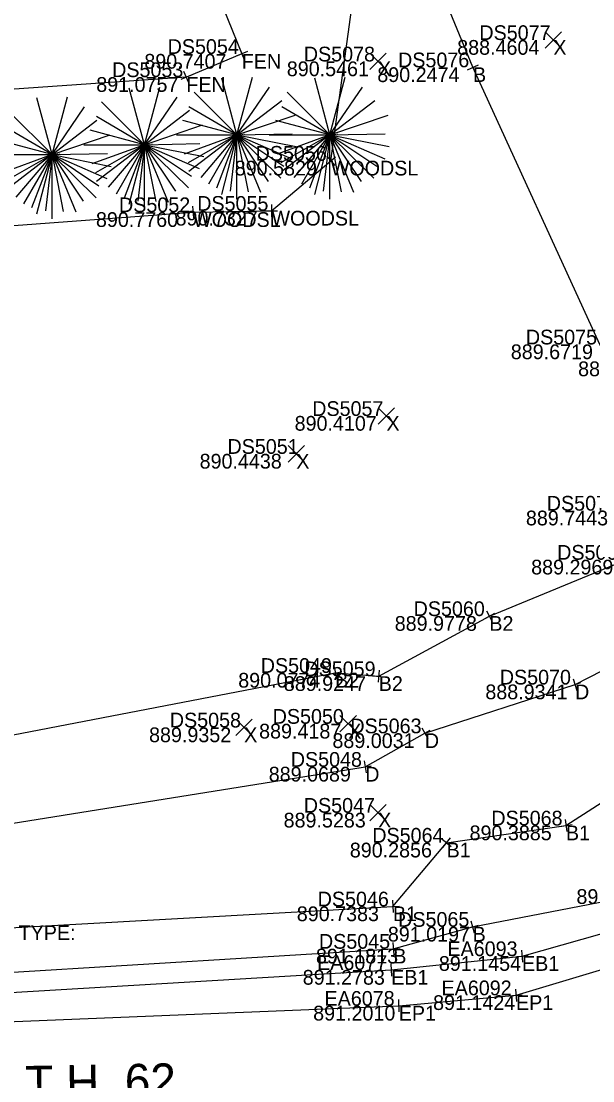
# Model space of a CAD drawing. Extents: x 179044 to 189691, y 286531 to 301257.
# Drawn here: x 180099.2 to 180145.7, y 300591.3 to 300677.6 of the extents above; entities that cross this region are included whole.
import ezdxf

# ---------------------------------------------------------------- set-up
doc = ezdxf.new("R2010")
doc.units = 0
for name, color, linetype in [('Default', 7, 'Continuous'), ('DR_X_Ditch', 7, 'Continuous'), ('PV_X_EOP', 7, 'Continuous'), ('PV_X_Shoulder_Aggregate', 7, 'Continuous'), ('RD_X_Fence', 7, 'Continuous'), ('SV_X_Break_Lines', 7, 'Continuous'), ('SV_X_Random_Point', 7, 'Continuous'), ('SV_X_Shot_Marker', 7, 'Continuous'), ('SV_X_Text_Comment', 7, 'Continuous'), ('SV_X_Text_Description', 7, 'Continuous'), ('SV_X_Text_Elevation', 7, 'Continuous'), ('SV_X_Text_Name', 7, 'Continuous'), ('VG_X_Cells', 7, 'Continuous'), ('VG_X_Text', 7, 'Continuous'), ('VG_X_Tree_Line_Rt', 7, 'Continuous')]:
    doc.layers.add(name, color=color, linetype=linetype)

msp = doc.modelspace()

# ---------------------------------------------------------------- linework, layer by layer
at = {"layer": 'DR_X_Ditch'}
msp.add_lwpolyline([(179564.56, 300599.962), (179672.339, 300603.26), (179771.172, 300605.494), (179880.337, 300606.441), (179984.937, 300607.328), (180077.947, 300608.965), (180127.19, 300616.843), (180132.045, 300619.573), (180144.286, 300623.545), (180155.547, 300629.29), (180160.465, 300633.547)], dxfattribs=at)
at = {"layer": 'PV_X_EOP'}
msp.add_lwpolyline([(179370.831, 300591.751), (179475.585, 300592.875), (179659.265, 300594.122), (179770.991, 300594.472), (179880.742, 300594.985), (179984.71, 300595.495), (180079.288, 300595.313), (180129.921, 300597.382), (180139.474, 300598.239), (180154.233, 300602.666), (180170.463, 300611.587), (180179.633, 300620.691), (180184.59, 300626.615), (180188.342, 300633.535), (180190.62, 300639.725), (180171.316, 300693.382), (180137.201, 300785.062), (180098.417, 300888.791)], dxfattribs=at)
at = {"layer": 'PV_X_Shoulder_Aggregate'}
msp.add_lwpolyline([(179563.565, 300594.924), (179658.987, 300595.359), (179770.596, 300596.259), (179881.565, 300597.129), (179984.257, 300597.357), (180079.139, 300597.322), (180129.307, 300600.299), (180139.964, 300601.425), (180153.02, 300605.118), (180169.97, 300613.883), (180177.635, 300623.691), (180181.654, 300635.111), (180182.998, 300649.235), (180167.771, 300692.69), (180134.639, 300784.201), (180095.484, 300888.508)], dxfattribs=at)
at = {"layer": 'RD_X_Fence'}
msp.add_lwpolyline([(180033.616, 300896.161), (180069.423, 300800.637), (180103.118, 300709.458), (180117.129, 300674.9), (180112.616, 300673.011), (180037.359, 300667.77), (179974.547, 300663.799), (179875.902, 300656.609), (179766.558, 300649.439), (179668.068, 300642.7), (179565.54, 300636.358)], dxfattribs=at)
at = {"layer": 'SV_X_Break_Lines'}
for points in [[(179564.638, 300606.986), (179671.768, 300606.922), (179771.087, 300608.912), (179880.599, 300615.611), (179986.884, 300616.02), (180078.033, 300615.521), (180124.742, 300624.492), (180128.289, 300624.221), (180137.303, 300629.118), (180148.459, 300633.708), (180154.503, 300636.496), (180146.307, 300651.241), (180135.969, 300673.811), (180118.542, 300716.074), (180095.911, 300772.35), (180076.611, 300824.96), (180047.5, 300900.199)], [(179564.191, 300598.682), (179770.809, 300601.942), (179880.33, 300600.557), (179984.707, 300602.17), (180076.298, 300602.513), (180129.447, 300605.473), (180133.823, 300610.665), (180143.543, 300612.063), (180154.911, 300619.358), (180168.807, 300625.749), (180172.898, 300631.66), (180174.527, 300641.071), (180168.307, 300660.619), (180157.537, 300688.57), (180123.865, 300779.294), (180087.271, 300883.216)], [(179564.385, 300595.92), (179672.75, 300596.68), (179770.459, 300597.562), (179880.51, 300598.544), (179984.703, 300599.007), (180076.342, 300598.773), (180129.476, 300602.027), (180135.94, 300603.814), (180151.807, 300606.879), (180162.976, 300612.722)]]:
    msp.add_lwpolyline(points, dxfattribs=at)
at = {"layer": 'SV_X_Random_Point'}
for p, q in [((180141.85, 300675.364), (180143.183, 300676.699)), ((180141.85, 300676.699), (180143.183, 300675.364)), ((180127.557, 300673.621), (180128.891, 300674.956)), ((180127.557, 300674.956), (180128.891, 300673.621)), ((180128.252, 300644.749), (180129.585, 300646.084)), ((180128.252, 300646.084), (180129.585, 300644.749)), ((180120.91, 300641.663), (180122.243, 300642.998)), ((180120.91, 300642.998), (180122.243, 300641.663)), ((180116.658, 300619.382), (180117.991, 300620.717)), ((180116.658, 300620.717), (180117.991, 300619.382)), ((180125.134, 300619.681), (180126.467, 300621.016)), ((180125.134, 300621.016), (180126.467, 300619.681)), ((180127.573, 300612.433), (180128.906, 300613.768)), ((180127.573, 300613.768), (180128.906, 300612.433))]:
    msp.add_line(p, q, dxfattribs=at)
at = {"layer": 'SV_X_Shot_Marker'}
for p, q in [((180117.592, 300675.088), (180116.665, 300674.712)), ((180116.941, 300675.364), (180117.317, 300674.437)), ((180117.129, 300674.9), (180117.129, 300674.9)), ((180135.514, 300673.603), (180136.423, 300674.02)), ((180136.177, 300673.357), (180135.76, 300674.266)), ((180135.969, 300673.811), (180135.969, 300673.811)), ((180113.077, 300673.204), (180112.155, 300672.818)), ((180112.809, 300672.55), (180112.423, 300673.472)), ((180112.616, 300673.011), (180112.616, 300673.011)), ((180124, 300665.879), (180124.765, 300666.523)), ((180124.06, 300666.583), (180124.705, 300665.819)), ((180124.383, 300666.201), (180124.383, 300666.201)), ((180113.13, 300662.509), (180113.204, 300661.511)), ((180119.541, 300662.624), (180119.559, 300661.624)), ((180112.668, 300661.973), (180113.666, 300662.047)), ((180113.167, 300662.01), (180113.167, 300662.01)), ((180119.05, 300662.115), (180120.05, 300662.133)), ((180119.55, 300662.124), (180119.55, 300662.124)), ((180136.864, 300628.879), (180137.742, 300629.356)), ((180137.064, 300629.557), (180137.542, 300628.678)), ((180137.303, 300629.118), (180137.303, 300629.118)), ((180124.251, 300624.398), (180125.233, 300624.587)), ((180124.648, 300624.983), (180124.837, 300624.001)), ((180124.742, 300624.492), (180124.742, 300624.492)), ((180128.327, 300624.72), (180128.25, 300623.723)), ((180127.79, 300624.259), (180128.787, 300624.183)), ((180128.289, 300624.221), (180128.289, 300624.221)), ((180143.81, 300623.391), (180144.761, 300623.699)), ((180144.132, 300624.02), (180144.44, 300623.069)), ((180144.286, 300623.545), (180144.286, 300623.545)), ((180131.609, 300619.328), (180132.481, 300619.818)), ((180131.8, 300620.009), (180132.29, 300619.137)), ((180132.045, 300619.573), (180132.045, 300619.573)), ((180126.696, 300616.764), (180127.683, 300616.922)), ((180127.111, 300617.337), (180127.269, 300616.35)), ((180127.19, 300616.843), (180127.19, 300616.843)), ((180143.472, 300612.558), (180143.614, 300611.568)), ((180143.048, 300611.992), (180144.038, 300612.134)), ((180143.543, 300612.063), (180143.543, 300612.063)), ((180133.441, 300610.988), (180134.205, 300610.343)), ((180133.501, 300610.283), (180134.145, 300611.048)), ((180133.823, 300610.665), (180133.823, 300610.665)), ((180129.42, 300605.972), (180129.475, 300604.974)), ((180128.948, 300605.445), (180129.947, 300605.501)), ((180129.447, 300605.473), (180129.447, 300605.473)), ((180135.458, 300603.681), (180136.422, 300603.947)), ((180135.807, 300604.296), (180136.073, 300603.332)), ((180135.94, 300603.814), (180135.94, 300603.814)), ((180128.977, 300601.997), (180129.975, 300602.058)), ((180129.445, 300602.526), (180129.507, 300601.528)), ((180129.476, 300602.027), (180129.476, 300602.027)), ((180139.467, 300601.372), (180140.462, 300601.478)), ((180139.912, 300601.922), (180140.017, 300600.928)), ((180139.964, 300601.425), (180139.964, 300601.425)), ((180128.808, 300600.27), (180129.806, 300600.329)), ((180129.277, 300600.799), (180129.337, 300599.8)), ((180129.307, 300600.299), (180129.307, 300600.299)), ((180139.429, 300598.737), (180139.519, 300597.741)), ((180129.901, 300597.882), (180129.941, 300596.882)), ((180138.976, 300598.194), (180139.972, 300598.284)), ((180139.474, 300598.239), (180139.474, 300598.239)), ((180129.421, 300597.362), (180130.421, 300597.402)), ((180129.921, 300597.382), (180129.921, 300597.382))]:
    msp.add_line(p, q, dxfattribs=at)
at = {"layer": 'VG_X_Cells'}
for p, q in [((180116.735, 300668.307), (180115.5, 300672.921)), ((180116.735, 300668.307), (180117.992, 300673.006)), ((180124.31, 300668.307), (180123.075, 300672.921)), ((180124.31, 300668.307), (180125.567, 300673.006)), ((180109.203, 300667.505), (180107.968, 300672.118)), ((180109.203, 300667.505), (180110.459, 300672.203)), ((180116.735, 300668.307), (180119.39, 300672.192)), ((180124.31, 300668.307), (180126.965, 300672.192)), ((180101.67, 300666.702), (180100.435, 300671.316)), ((180101.67, 300666.702), (180102.927, 300671.401)), ((180109.203, 300667.505), (180111.858, 300671.39)), ((180116.735, 300668.307), (180113.245, 300671.794)), ((180116.735, 300668.307), (180120.392, 300671.112)), ((180124.31, 300668.307), (180120.82, 300671.794)), ((180124.31, 300668.307), (180127.967, 300671.112)), ((180101.67, 300666.702), (180104.325, 300670.587)), ((180109.203, 300667.505), (180105.713, 300670.992)), ((180109.203, 300667.505), (180112.859, 300670.31)), ((180116.735, 300668.307), (180112.829, 300670.604)), ((180124.31, 300668.307), (180120.404, 300670.604)), ((180101.67, 300666.702), (180098.18, 300670.189)), ((180101.67, 300666.702), (180105.327, 300669.507)), ((180109.203, 300667.505), (180105.296, 300669.802)), ((180116.735, 300668.307), (180112.322, 300669.491)), ((180116.735, 300668.307), (180121.472, 300669.914)), ((180124.31, 300668.307), (180119.897, 300669.491)), ((180124.31, 300668.307), (180129.047, 300669.914)), ((180101.67, 300666.702), (180097.763, 300668.999)), ((180109.203, 300667.505), (180104.789, 300668.688)), ((180109.203, 300667.505), (180113.939, 300669.112)), ((180101.67, 300666.702), (180097.257, 300667.886)), ((180101.67, 300666.702), (180106.407, 300668.309)), ((180111.8, 300668.307), (180116.735, 300668.307)), ((180116.735, 300668.307), (180112.445, 300666.746)), ((180116.735, 300668.307), (180112.752, 300666.026)), ((180116.735, 300668.307), (180112.829, 300665.312)), ((180116.735, 300668.307), (180113.79, 300664.841)), ((180116.735, 300668.307), (180114.417, 300664.292)), ((180116.735, 300668.307), (180115.07, 300663.967)), ((180116.735, 300668.307), (180115.472, 300663.451)), ((180116.735, 300668.307), (180116.194, 300663.716)), ((180116.735, 300668.307), (180121.245, 300668.399)), ((180116.735, 300663.067), (180116.735, 300668.307)), ((180116.735, 300668.307), (180117.657, 300663.671)), ((180116.735, 300668.307), (180118.669, 300663.639)), ((180116.735, 300668.307), (180119.272, 300664.514)), ((180116.735, 300668.307), (180120.324, 300664.786)), ((180116.735, 300668.307), (180120.557, 300665.752)), ((180116.735, 300668.307), (180121.2, 300666.366)), ((180116.735, 300668.307), (180121.564, 300667.349)), ((180119.375, 300668.307), (180124.31, 300668.307)), ((180124.31, 300668.307), (180120.02, 300666.746)), ((180124.31, 300668.307), (180120.327, 300666.026)), ((180124.31, 300668.307), (180120.404, 300665.312)), ((180124.31, 300668.307), (180121.365, 300664.841)), ((180124.31, 300668.307), (180121.992, 300664.292)), ((180124.31, 300668.307), (180122.645, 300663.967)), ((180124.31, 300668.307), (180123.047, 300663.451)), ((180124.31, 300668.307), (180123.769, 300663.716)), ((180124.31, 300668.307), (180128.82, 300668.399)), ((180124.31, 300663.067), (180124.31, 300668.307)), ((180124.31, 300668.307), (180125.232, 300663.671)), ((180124.31, 300668.307), (180126.244, 300663.639)), ((180124.31, 300668.307), (180126.847, 300664.514)), ((180124.31, 300668.307), (180127.899, 300664.786)), ((180124.31, 300668.307), (180128.132, 300665.752)), ((180124.31, 300668.307), (180128.775, 300666.366)), ((180124.31, 300668.307), (180129.139, 300667.349)), ((180101.67, 300666.702), (180106.18, 300666.794)), ((180104.268, 300667.505), (180109.203, 300667.505)), ((180109.203, 300667.505), (180104.913, 300665.943)), ((180109.203, 300667.505), (180105.219, 300665.223)), ((180109.203, 300667.505), (180105.296, 300664.51)), ((180109.203, 300667.505), (180106.258, 300664.038)), ((180109.203, 300667.505), (180106.884, 300663.49)), ((180109.203, 300667.505), (180107.538, 300663.165)), ((180109.203, 300667.505), (180107.939, 300662.648)), ((180109.203, 300667.505), (180108.661, 300662.913)), ((180109.203, 300667.505), (180113.713, 300667.597)), ((180109.203, 300662.265), (180109.203, 300667.505)), ((180109.203, 300667.505), (180110.124, 300662.868)), ((180109.203, 300667.505), (180111.136, 300662.837)), ((180109.203, 300667.505), (180111.739, 300663.712)), ((180109.203, 300667.505), (180112.791, 300663.983)), ((180109.203, 300667.505), (180113.024, 300664.95)), ((180109.203, 300667.505), (180113.668, 300665.563)), ((180109.203, 300667.505), (180114.031, 300666.547)), ((180096.735, 300666.702), (180101.67, 300666.702)), ((180101.67, 300666.702), (180097.38, 300665.141)), ((180101.67, 300666.702), (180097.687, 300664.421)), ((180101.67, 300666.702), (180097.763, 300663.707)), ((180101.67, 300666.702), (180098.725, 300663.236)), ((180101.67, 300666.702), (180099.352, 300662.687)), ((180101.67, 300666.702), (180100.005, 300662.362)), ((180101.67, 300666.702), (180100.407, 300661.846)), ((180101.67, 300666.702), (180101.128, 300662.111)), ((180101.67, 300661.462), (180101.67, 300666.702)), ((180101.67, 300666.702), (180102.592, 300662.066)), ((180101.67, 300666.702), (180103.603, 300662.034)), ((180101.67, 300666.702), (180104.207, 300662.909)), ((180101.67, 300666.702), (180105.258, 300663.181)), ((180101.67, 300666.702), (180105.492, 300664.147)), ((180101.67, 300666.702), (180106.135, 300664.761)), ((180101.67, 300666.702), (180106.498, 300665.744))]:
    msp.add_line(p, q, dxfattribs=at)
at = {"layer": 'VG_X_Tree_Line_Rt'}
msp.add_lwpolyline([(179653.026, 300638.702), (179657.624, 300631.959), (179767.935, 300639.504), (179876.981, 300645.549), (179982.655, 300652.223), (180074.045, 300659.112), (180113.167, 300662.01), (180119.55, 300662.124), (180124.383, 300666.201), (180126.147, 300679.098), (180114.54, 300714.374), (180093.362, 300771.604), (180073.514, 300824.308), (180043.465, 300899.612)], dxfattribs=at)

# ---------------------------------------------------------------- texts
at = {"layer": 'Default'}
msp.add_text('T.H. 62', height=2.8, rotation=1.06539, dxfattribs=at).set_placement((180099.516, 300589.678))
at = {"layer": 'SV_X_Text_Comment'}
for s, height, p in [('X', 1.2, (180142.517, 300674.832)), ('FEN', 1.2, (180117.129, 300673.7)), ('X', 1.2, (180128.224, 300673.088)), ('B', 1.2, (180135.969, 300672.611)), ('FEN', 1.2, (180112.616, 300671.811)), ('TE', 0.12, (180116.735, 300668.187)), ('TE', 0.12, (180124.31, 300668.187)), ('TE', 0.12, (180109.203, 300667.385)), ('TE', 0.12, (180101.67, 300666.582)), ('WOODSL', 1.2, (180124.383, 300665.001)), ('WOODSL', 1.2, (180113.167, 300660.81)), ('WOODSL', 1.2, (180119.55, 300660.924)), ('X', 1.2, (180128.919, 300644.216)), ('X', 1.2, (180121.577, 300641.131)), ('B2', 1.2, (180137.303, 300627.918)), ('B2', 1.2, (180124.742, 300623.292)), ('B2', 1.2, (180128.289, 300623.021)), ('D', 1.2, (180144.286, 300622.345)), ('X', 1.2, (180125.8, 300619.148)), ('X', 1.2, (180117.324, 300618.849)), ('D', 1.2, (180132.045, 300618.373)), ('D', 1.2, (180127.19, 300615.643)), ('X', 1.2, (180128.24, 300611.901)), ('B1', 1.2, (180143.543, 300610.863)), ('B1', 1.2, (180133.823, 300609.465)), ('B1', 1.2, (180129.447, 300604.273)), ('B', 1.2, (180135.94, 300602.614)), ('B', 1.2, (180129.476, 300600.827)), ('EB1', 1.2, (180139.964, 300600.225)), ('EB1', 1.2, (180129.307, 300599.099)), ('EP1', 1.2, (180139.474, 300597.039)), ('EP1', 1.2, (180129.921, 300596.182))]:
    msp.add_text(s, height=height, dxfattribs=at).set_placement(p)
at = {"layer": 'SV_X_Text_Description'}
msp.add_text('Vehicle Weight Limit 10 Tons TYPE:', height=1.2, dxfattribs=at).set_placement((180077.723, 300602.73))
at = {"layer": 'SV_X_Text_Elevation'}
for s, p in [('888.4604', (180134.684, 300674.832)), ('890.7407', (180109.192, 300673.7)), ('890.5461', (180120.801, 300673.088)), ('890.2474', (180128.174, 300672.611)), ('891.0757', (180105.275, 300671.811)), ('890.5829', (180116.559, 300665.001)), ('890.7760', (180105.249, 300660.81)), ('890.7327', (180111.736, 300660.924)), ('889.6719', (180139.051, 300650.041)), ('888.3098', (180144.534, 300648.653)), ('890.4107', (180121.437, 300644.216)), ('890.4438', (180113.697, 300641.131)), ('889.7443', (180140.282, 300636.506)), ('889.2969', (180140.711, 300632.508)), ('889.9778', (180129.593, 300627.918)), ('890.0774', (180116.843, 300623.292)), ('889.9247', (180120.56, 300623.021)), ('888.9341', (180136.976, 300622.345)), ('889.4187', (180118.545, 300619.148)), ('889.9352', (180109.577, 300618.849)), ('889.0031', (180124.517, 300618.373)), ('889.0689', (180119.329, 300615.643)), ('889.5283', (180120.54, 300611.901)), ('890.3885', (180135.691, 300610.863)), ('890.2856', (180125.934, 300609.465)), ('891.0638', (180144.4, 300605.679)), ('890.7383', (180121.615, 300604.273)), ('891.0197', (180129.034, 300602.614)), ('891.1813', (180123.176, 300600.827)), ('891.1454', (180133.191, 300600.225)), ('891.2783', (180122.099, 300599.099)), ('891.1424', (180132.72, 300597.039)), ('891.2010', (180122.949, 300596.182))]:
    msp.add_text(s, height=1.2, dxfattribs=at).set_placement(p)
at = {"layer": 'SV_X_Text_Name'}
for s, p in [('DS5077', (180136.489, 300676.032)), ('DS5054', (180111.091, 300674.9)), ('DS5078', (180122.187, 300674.288)), ('DS5076', (180129.865, 300673.811)), ('DS5053', (180106.569, 300673.011)), ('DS5056', (180118.26, 300666.201)), ('DS5055', (180113.503, 300662.124)), ('DS5052', (180107.13, 300662.01)), ('DS5075', (180140.279, 300651.241)), ('DS5057', (180122.872, 300645.416)), ('DS5051', (180115.968, 300642.331)), ('DS5074', (180141.982, 300637.706)), ('DS5061', (180142.83, 300633.708)), ('DS5060', (180131.133, 300629.118)), ('DS5049', (180118.677, 300624.492)), ('DS5059', (180122.232, 300624.221)), ('DS5070', (180138.154, 300623.545)), ('DS5058', (180111.268, 300620.049)), ('DS5050', (180119.65, 300620.348)), ('DS5063', (180125.979, 300619.573)), ('DS5048', (180121.124, 300616.843)), ('DS5047', (180122.184, 300613.101)), ('DS5068', (180137.468, 300612.063)), ('DS5064', (180127.767, 300610.665)), ('DS5046', (180123.316, 300605.473)), ('DS5065', (180129.874, 300603.814)), ('DS5045', (180123.42, 300602.027)), ('EA6093', (180133.889, 300601.425)), ('EA6077', (180123.27, 300600.299)), ('EA6092', (180133.408, 300598.239)), ('EA6078', (180123.874, 300597.382))]:
    msp.add_text(s, height=1.2, dxfattribs=at).set_placement(p)
at = {"layer": 'VG_X_Text'}
for p in [(180116.735, 300668.307), (180124.31, 300668.307), (180101.67, 300666.702), (180109.203, 300667.505)]:
    msp.add_text(' NOTE:8', height=0.12, dxfattribs=at).set_placement(p)

doc.saveas('drawing.dxf')
